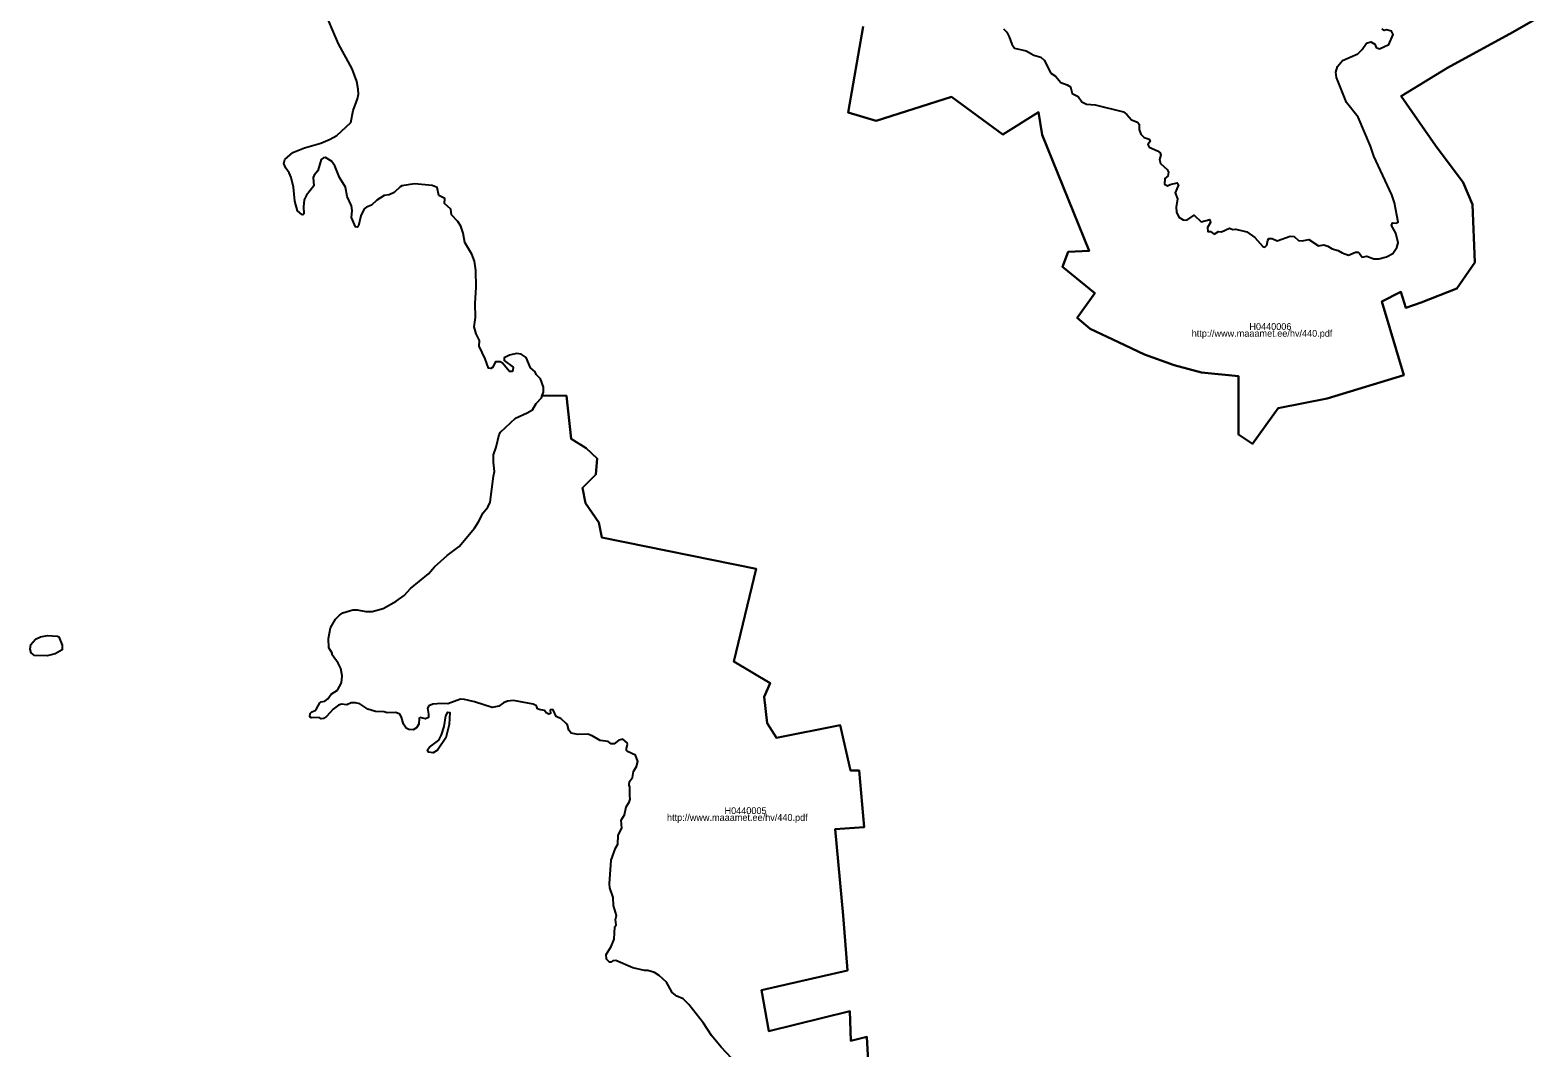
# Model space of a CAD drawing. Extents: x 369010 to 739155, y 6377141 to 6634081.
# Drawn here: x 371724 to 377260, y 6460752 to 6464489 of the extents above; entities that cross this region are included whole.
import ezdxf

# ---------------------------------------------------------------- set-up
doc = ezdxf.new("R2010")
doc.units = 0
for name, color, linetype in [('H_LINK', 7, 'Continuous'), ('H_PIIR', 7, 'Continuous'), ('H_TUNNUS', 7, 'Continuous')]:
    doc.layers.add(name, color=color, linetype=linetype)

msp = doc.modelspace()

# ---------------------------------------------------------------- linework, layer by layer
at = {"layer": 'H_PIIR'}
for points in [[(374809.34, 6460544.78), (374796.65, 6460792.3), (374738.0399, 6460777.6401), (374734.27, 6460887.3201), (374436.2199, 6460813.02), (374409.8101, 6460963.3801), (374724.8401, 6461035.91), (374709.7499, 6461237.57), (374679.55, 6461555.05), (374787.0799, 6461562.13), (374768.21, 6461770.86), (374736.15, 6461770.86), (374698.42, 6461937.14), (374464.5099, 6461891.1499), (374430.5501, 6461944.2199), (374419.23, 6462041.51), (374441.87, 6462091.04), (374307.94, 6462170.65), (374389.5099, 6462511.4401), (373823.6001, 6462626.43), (373812.28, 6462681.26), (373763.24, 6462752.0201), (373751.9199, 6462808.6301), (373800.9699, 6462858.1599), (373806.62, 6462916.5301), (373765.3701, 6462954.77), (373710.66, 6462988.38), (373693.87, 6463147.08), (373604.2785, 6463147.6482), (373608.47, 6463160.2347), (373609.4599, 6463178.7346), (373598.5601, 6463209.1247), (373582.3799, 6463224.6547), (373578.74, 6463234.5647), (373561.9, 6463249.7646), (373545.71, 6463287.0847), (373527.5399, 6463299.9746), (373510.3601, 6463301.6246), (373484.6, 6463295.3446), (373464.1201, 6463285.7647), (373464.1201, 6463276.8446), (373497.81, 6463252.0746), (373496.4901, 6463240.8447), (373494.4, 6463235.5747), (373483.94, 6463235.8846), (373458.17, 6463266.9347), (373450.2399, 6463271.2346), (373433.0601, 6463270.9047), (373421.83, 6463250.4246), (373415.5599, 6463246.4546), (373406.64, 6463248.1046), (373395.08, 6463282.4647), (373372.2799, 6463328.7147), (373373.93, 6463350.1846), (373361.71, 6463374.2947), (373354.11, 6463400.0647), (373359.7301, 6463434.4146), (373357.75, 6463485.9546), (373361.3799, 6463546.0747), (373360.7199, 6463606.1947), (373355.44, 6463640.5446), (373345.8601, 6463666.3146), (373320.75, 6463709.2646), (373313.81, 6463743.6146), (373305.5501, 6463769.3847), (373294.32, 6463786.5646), (373270.8701, 6463811.6646), (373268.23, 6463832.1446), (373245.1, 6463852.6246), (373246.75, 6463871.4547), (373224.6199, 6463882.6846), (373219.0001, 6463912.0846), (373199.8501, 6463919.0246), (373135.1, 6463924.9746), (373088.85, 6463917.3746), (373082.2401, 6463913.7447), (373060.44, 6463893.2546), (373042.6, 6463884.3447), (373024.11, 6463881.6946), (372997.3501, 6463865.5146), (372977.53, 6463847.0146), (372959.3601, 6463839.7447), (372951.0999, 6463833.7946), (372938.22, 6463807.7046), (372929.96, 6463770.7046), (372926.3199, 6463765.7446), (372918.4, 6463767.4046), (372903.53, 6463801.7547), (372906.8401, 6463827.5246), (372903.53, 6463844.7046), (372888.67, 6463879.0547), (372881.73, 6463913.4046), (372859.6, 6463947.7647), (372843.08, 6463990.7046), (372831.1901, 6464007.8846), (372808.39, 6464022.0947), (372801.7901, 6464021.1046), (372793.2, 6464014.4947), (372780.65, 6463972.8746), (372767.43, 6463957.0147), (372763.1401, 6463948.4246), (372765.78, 6463918.0346), (372739.3499, 6463884.0046), (372730.7601, 6463866.5046), (372727.7899, 6463840.7346), (372729.1101, 6463814.9647), (372725.81, 6463811.3346), (372721.5199, 6463811.9947), (372706.32, 6463826.2046), (372696.41, 6463861.8746), (372691.12, 6463913.4046), (372682.54, 6463947.7647), (372674.61, 6463964.9447), (372662.38, 6463982.1246), (372655.45, 6463999.2946), (372658.7501, 6464014.4947), (372688.48, 6464039.9247), (372731.4301, 6464056.7747), (372791.55, 6464074.9446), (372825.8999, 6464089.4846), (372849.6901, 6464102.3647), (372901.22, 6464149.7646), (372910.47, 6464194.1946), (372926, 6464237.1446), (372929.63, 6464254.3246), (372928.97, 6464272.8146), (372923.68, 6464300.5646), (372906.1801, 6464346.8146), (372856.6201, 6464439.3047), (372798.52, 6464574.3547)], [(377260.1601, 6464535.03), (377167.7299, 6464481.96), (376928.16, 6464351.05), (376758.5699, 6464247.5399), (376884.9599, 6464065.34), (376986.4999, 6463929.5599), (377020.81, 6463849.67), (377029.11, 6463635.8899), (376962.2499, 6463540.38), (376832.09, 6463489.08), (376775.73, 6463469.6799), (376757.27, 6463528.34), (376686.92, 6463493.29), (376767.9501, 6463221.97), (376486.8799, 6463137.06), (376306.2499, 6463101.5699), (376211.93, 6462970.6699), (376161.0001, 6463004.28), (376161.0001, 6463218.33), (376025.18, 6463232.48), (375925.21, 6463259.01), (375816.32, 6463298.85), (375720.1101, 6463343.07), (375616.3601, 6463392.6), (375569.2, 6463433.29), (375633.34, 6463523.5001), (375514.5, 6463620.8), (375535.25, 6463675.63), (375612.59, 6463679.1699), (375439.5699, 6464105.0601), (375426.3699, 6464188.2001), (375296.21, 6464106.8301), (375107.57, 6464244.81), (374830.9901, 6464156.3699), (374727.24, 6464186.4401), (374782.6101, 6464502.41)], [(374782.6101, 6464502.41), (374727.24, 6464186.4401), (374830.9901, 6464156.3699), (375107.57, 6464244.81), (375296.21, 6464106.8301), (375426.3699, 6464188.2001), (375439.5699, 6464105.0601), (375612.59, 6463679.1699), (375535.25, 6463675.63), (375514.5, 6463620.8), (375633.34, 6463523.5001), (375569.2, 6463433.29), (375616.3601, 6463392.6), (375720.1101, 6463343.07), (375816.32, 6463298.85), (375925.21, 6463259.01), (376025.18, 6463232.48), (376161.0001, 6463218.33), (376161.0001, 6463004.28), (376211.93, 6462970.6699), (376306.2499, 6463101.5699), (376486.8799, 6463137.06), (376767.9501, 6463221.97), (376686.92, 6463493.29), (376757.27, 6463528.34), (376775.73, 6463469.6799), (376832.09, 6463489.08), (376962.2499, 6463540.38), (377029.11, 6463635.8899), (377020.81, 6463849.67), (376986.4999, 6463929.5599), (376884.9599, 6464065.34), (376758.5699, 6464247.5399), (376928.16, 6464351.05), (377167.7299, 6464481.96), (377260.1601, 6464535.03)], [(375298.49, 6464493.8146), (375310.03, 6464481.9447), (375319.1701, 6464464.9046), (375328.2, 6464437.8146), (375338.6499, 6464423.0847), (375380.9501, 6464413.5746), (375409.46, 6464397.4146), (375434.64, 6464389.8146), (375447.2301, 6464378.8746), (375472.42, 6464331.3447), (375489.05, 6464319.9447), (375508.54, 6464296.6547), (375531.82, 6464289.0446), (375543.7, 6464280.9746), (375550.3499, 6464256.2547), (375571.7399, 6464245.3247), (375585.7501, 6464225.8347), (375602.3799, 6464217.7547), (375634.2201, 6464215.3847), (375738.5199, 6464189.2346), (375751.3501, 6464179.7347), (375768.4599, 6464160.2446), (375789.8399, 6464151.6946), (375796.5, 6464144.0846), (375796.5, 6464124.1247), (375802.2, 6464107.9647), (375815.03, 6464095.6146), (375833.56, 6464089.4346), (375836.41, 6464079.9247), (375828.33, 6464069.9447), (375833.56, 6464059.4947), (375863.98, 6464046.6546), (375873.4799, 6464039.0546), (375875.61, 6464030.0246), (375870.86, 6464014.3446), (375874.1901, 6463999.6047), (375899.37, 6463977.2746), (375903.6501, 6463967.7647), (375901.2701, 6463953.0346), (375890.3401, 6463944.4746), (375889.39, 6463923.5647), (375900.8001, 6463917.8646), (375910.3, 6463923.0946), (375935.9601, 6463928.3146), (375940.72, 6463921.6647), (375928.84, 6463892.1947), (375936.4399, 6463869.3846), (375931.69, 6463839.9147), (375933.5901, 6463820.4346), (375941.6701, 6463802.3747), (375957.8201, 6463792.3947), (375971.1301, 6463791.4347), (375997.7401, 6463809.5046), (376023.4, 6463785.7346), (376055.2399, 6463793.8146), (376058.0899, 6463783.3647), (376046.6901, 6463765.2947), (376048.11, 6463749.6146), (376058.58, 6463750.0946), (376071.88, 6463740.5847), (376087.5599, 6463750.5646), (376098.97, 6463749.1347), (376127.4801, 6463762.4447), (376140.31, 6463757.6946), (376151.24, 6463759.1247), (376191.16, 6463748.1846), (376220.3801, 6463727.7447), (376249.8401, 6463694.9547), (376257.44, 6463692.5747), (376265.05, 6463699.7047), (376268.8501, 6463718.7147), (376272.1799, 6463724.4247), (376284.53, 6463724.4247), (376302.59, 6463715.8647), (376351.06, 6463733.4546), (376365.7901, 6463731.5546), (376381.71, 6463717.2946), (376394.5399, 6463715.8746), (376419.73, 6463721.0946), (376454.42, 6463696.8546), (376474.1399, 6463700.6547), (376489.35, 6463696.3846), (376504.56, 6463686.8747), (376526.42, 6463679.7446), (376541.1501, 6463671.6646), (376565.3801, 6463663.5846), (376590.0999, 6463674.0446), (376598.65, 6463673.5647), (376605.55, 6463669.2846), (376614.57, 6463655.9846), (376632.16, 6463658.8346), (376658.2901, 6463649.8046), (376676.35, 6463649.8046), (376703.9101, 6463656.4546), (376727.68, 6463669.2846), (376741.9299, 6463690.6746), (376746.92, 6463708.2647), (376738.3699, 6463744.3846), (376722.69, 6463771.4746), (376726.49, 6463782.4046), (376742.17, 6463780.0346), (376747.87, 6463784.3047), (376733.62, 6463855.1246), (376723.87, 6463885.0646), (376657.5799, 6464026.2247), (376645.22, 6464063.7647), (376599.84, 6464169.2747), (376558.02, 6464223.9347), (376520.24, 6464316.1346), (376518.34, 6464335.1446), (376524.9901, 6464356.0546), (376543.05, 6464377.9146), (376599.12, 6464402.1546), (376615.28, 6464417.8347), (376630.4899, 6464441.1247), (376646.41, 6464446.3546), (376661.1399, 6464437.8046), (376666.3701, 6464425.4447), (376678.25, 6464421.1646), (376713.41, 6464436.3747), (376729.1, 6464473.9247), (376722.9201, 6464486.2746), (376704.86, 6464490.0847), (376695.36, 6464488.6546), (376687.7501, 6464492.9347)], [(374319.03, 6460693.9246), (374261.22, 6460755.0446), (374225.55, 6460797.9847), (374196.15, 6460843.2446), (374142.96, 6460911.2946), (374122.15, 6460932.4347), (374098.6999, 6460942.3446), (374081.19, 6460955.2246), (374060.7101, 6460993.2146), (374033.29, 6461018.3247), (374016.44, 6461028.5646), (373991.9999, 6461036.4946), (373980.1, 6461035.8246), (373936.5, 6461045.4047), (373875.06, 6461072.8246), (373863.5, 6461072.1646), (373856.5601, 6461067.2146), (373850.94, 6461067.2146), (373840.7, 6461077.7847), (373839.38, 6461095.2946), (373857.88, 6461124.3646), (373868.78, 6461151.1147), (373871.4199, 6461197.0346), (373875.72, 6461203.3146), (373873.0799, 6461223.7947), (373876.7101, 6461238.3246), (373866.47, 6461274.6646), (373864.82, 6461303.7346), (373852.9199, 6461340.0746), (373850.94, 6461354.6046), (373857.22, 6461441.8147), (373873.7399, 6461485.4246), (373882.3199, 6461499.6247), (373882.66, 6461533.3246), (373896.8601, 6461559.0847), (373894.5501, 6461587.8247), (373906.77, 6461607.3146), (373912.72, 6461637.3747), (373923.9499, 6461653.8946), (373927.25, 6461665.1247), (373925.5999, 6461677.6746), (373926.59, 6461709.3946), (373923.62, 6461716.9847), (373925.27, 6461729.8747), (373935.5101, 6461744.7347), (373939.8, 6461767.5346), (373950.7, 6461785.0347), (373954.9999, 6461803.2046), (373947.4, 6461826.6647), (373917.34, 6461839.8747), (373914.37, 6461843.8346), (373913.71, 6461851.4347), (373918, 6461867.6247), (373916.02, 6461872.2447), (373900.49, 6461885.1346), (373886.29, 6461881.8246), (373868.4499, 6461868.9447), (373857.5499, 6461868.2847), (373846.98, 6461877.5347), (373817.58, 6461880.8347), (373787.8501, 6461898.3447), (373771.33, 6461904.2946), (373734.99, 6461902.3047), (373711.21, 6461907.2646), (373702.2899, 6461918.4947), (373696.6701, 6461936.6646), (373692.0501, 6461943.6046), (373673.5501, 6461960.7746), (373655.38, 6461969.3646), (373645.14, 6461993.4847), (373636.5499, 6461994.1447), (373633.91, 6461991.8247), (373634.9001, 6461980.2647), (373628.6201, 6461977.6246), (373618.38, 6461982.2546), (373612.4401, 6461990.5047), (373592.95, 6461994.1447), (373587.33, 6461997.4447), (373583.37, 6462008.6746), (373571.15, 6462014.6246), (373498.47, 6462027.8346), (373476.67, 6462025.5246), (373462.13, 6462019.5746), (373444.63, 6462006.3646), (373420.1799, 6462001.7446), (373355.76, 6462023.2146), (373319.43, 6462031.8046), (373304.8901, 6462032.1347), (373257.98, 6462014.9546), (373234.2, 6462016.2746), (373202.49, 6462013.6347), (373188.61, 6462008.6746), (373182.9999, 6461999.4246), (373186.96, 6461977.6246), (373186.3, 6461965.4046), (373176.39, 6461959.7846), (373156.5701, 6461965.7347), (373152.94, 6461962.4247), (373151.62, 6461941.2846), (373143.03, 6461927.7447), (373130.48, 6461920.4746), (373114.62, 6461921.4646), (373104.38, 6461926.4247), (373094.47, 6461940.9547), (373087.2, 6461967.0546), (373081.5801, 6461976.9646), (373066.39, 6461983.2446), (373034.68, 6461982.5847), (373024.4399, 6461985.8847), (372992.7201, 6461986.8746), (372964.64, 6461995.7947), (372934.58, 6462015.9447), (372918.4, 6462019.2446), (372902.54, 6462019.2446), (372886.68, 6462011.6546), (372867.19, 6462014.2947), (372856.29, 6462009.9946), (372837.13, 6461995.7947), (372812.36, 6461968.7047), (372801.46, 6461961.4346), (372793.2, 6461960.7746), (372785.36, 6461965.1447), (372757.1899, 6461964.0847), (372751.5801, 6461967.7146), (372752.5699, 6461980.2647), (372758.84, 6461986.5447), (372770.4, 6461991.5046), (372775.6899, 6461996.7846), (372787.58, 6462018.9147), (372791.8799, 6462022.2247), (372806.08, 6462025.1947), (372816.98, 6462034.1146), (372829.87, 6462050.6247), (372852.66, 6462065.1646), (372867.86, 6462092.5847), (372870.16, 6462117.9747), (372864.6501, 6462145.0346), (372854.64, 6462164.2647), (372833.5001, 6462195.6446), (372832.51, 6462201.9246), (372821.2799, 6462221.4147), (372819.6301, 6462255.7746), (372827.55, 6462294.0847), (372845.35, 6462326.2847), (372860.29, 6462340.8547), (372872.8101, 6462349.2546), (372909.1501, 6462360.8146), (372925, 6462360.1546), (372956.72, 6462354.2146), (372980.4999, 6462354.2146), (373019.8099, 6462365.4446), (373068.68, 6462392.7647), (373097.44, 6462413.3446), (373121.22, 6462438.7747), (373187.29, 6462492.2946), (373209.0399, 6462518.7246), (373255.01, 6462560.4446), (373298.95, 6462593.3746), (373355.1201, 6462660.9947), (373370.6301, 6462683.5647), (373387.4801, 6462717.2546), (373404.99, 6462738.0646), (373413.2399, 6462755.6347), (373425.14, 6462851.7046), (373429.1, 6462868.8846), (373425.14, 6462903.2347), (373425.8, 6462930.3246), (373435.38, 6462958.0747), (373446.2801, 6463004.3147), (373450.9001, 6463013.5647), (373505.7401, 6463064.7646), (373548.68, 6463083.5946), (373568.17, 6463094.8347), (373581.7199, 6463118.6147), (373601.5401, 6463139.4247), (373604.2785, 6463147.6482), (373693.87, 6463147.08), (373710.66, 6462988.38), (373765.3701, 6462954.77), (373806.62, 6462916.5301), (373800.9699, 6462858.1599), (373751.9199, 6462808.6301), (373763.24, 6462752.0201), (373812.28, 6462681.26), (373823.6001, 6462626.43), (374389.5099, 6462511.4401), (374307.94, 6462170.65), (374441.87, 6462091.04), (374419.23, 6462041.51), (374430.5501, 6461944.2199), (374464.5099, 6461891.1499), (374698.42, 6461937.14), (374736.15, 6461770.86), (374768.21, 6461770.86), (374787.0799, 6461562.13), (374679.55, 6461555.05), (374709.7499, 6461237.57), (374724.8401, 6461035.91), (374409.8101, 6460963.3801), (374436.2199, 6460813.02), (374734.27, 6460887.3201), (374738.0399, 6460777.6401), (374796.65, 6460792.3), (374809.34, 6460544.78)]]:
    msp.add_lwpolyline(points, dxfattribs=at)
for points in [[(371824.2711, 6462263.9968), (371829.5673, 6462261.6797), (371842.1456, 6462230.7305), (371841.1526, 6462213.5181), (371815.6651, 6462198.6227), (371786.7018, 6462192.0024), (371740.6916, 6462193.3265), (371727.7824, 6462202.5948), (371724.1412, 6462216.1661), (371726.1274, 6462233.0474), (371743.6707, 6462252.4114), (371762.2073, 6462261.3486), (371787.3639, 6462265.9827)], [(373250.9157, 6461890.2886), (373219.3044, 6461845.1061), (373204.4091, 6461835.5069), (373186.7, 6461837.824), (373183.39, 6461846.7611), (373190.6721, 6461856.6914), (373224.2695, 6461882.5101), (373234.8619, 6461902.0394), (373244.13, 6461931.9956), (373250.4191, 6461971.0547), (373258.0324, 6461984.9571), (373264.9836, 6461983.302), (373262.3354, 6461939.9398)]]:
    msp.add_lwpolyline(points, close=True, dxfattribs=at)

# ---------------------------------------------------------------- texts
at = {"layer": 'H_LINK'}
for rotation, p in [(360, (375989.1662, 6463363.5181)), (0, (374062.5855, 6461585.6014))]:
    msp.add_text('http://www.maaamet.ee/hv/440.pdf', height=25, rotation=rotation, dxfattribs=at).set_placement(p)
at = {"layer": 'H_TUNNUS'}
for s, rotation, p in [('H0440006', 360, (376201.0208, 6463388.5181)), ('H0440005', 0, (374273.8144, 6461610.6014))]:
    msp.add_text(s, height=25, rotation=rotation, dxfattribs=at).set_placement(p)

doc.saveas('drawing.dxf')
